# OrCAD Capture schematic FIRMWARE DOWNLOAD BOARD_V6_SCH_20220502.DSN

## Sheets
1 1. TITLE: title: Atmosic MP Download Board; rev: 06
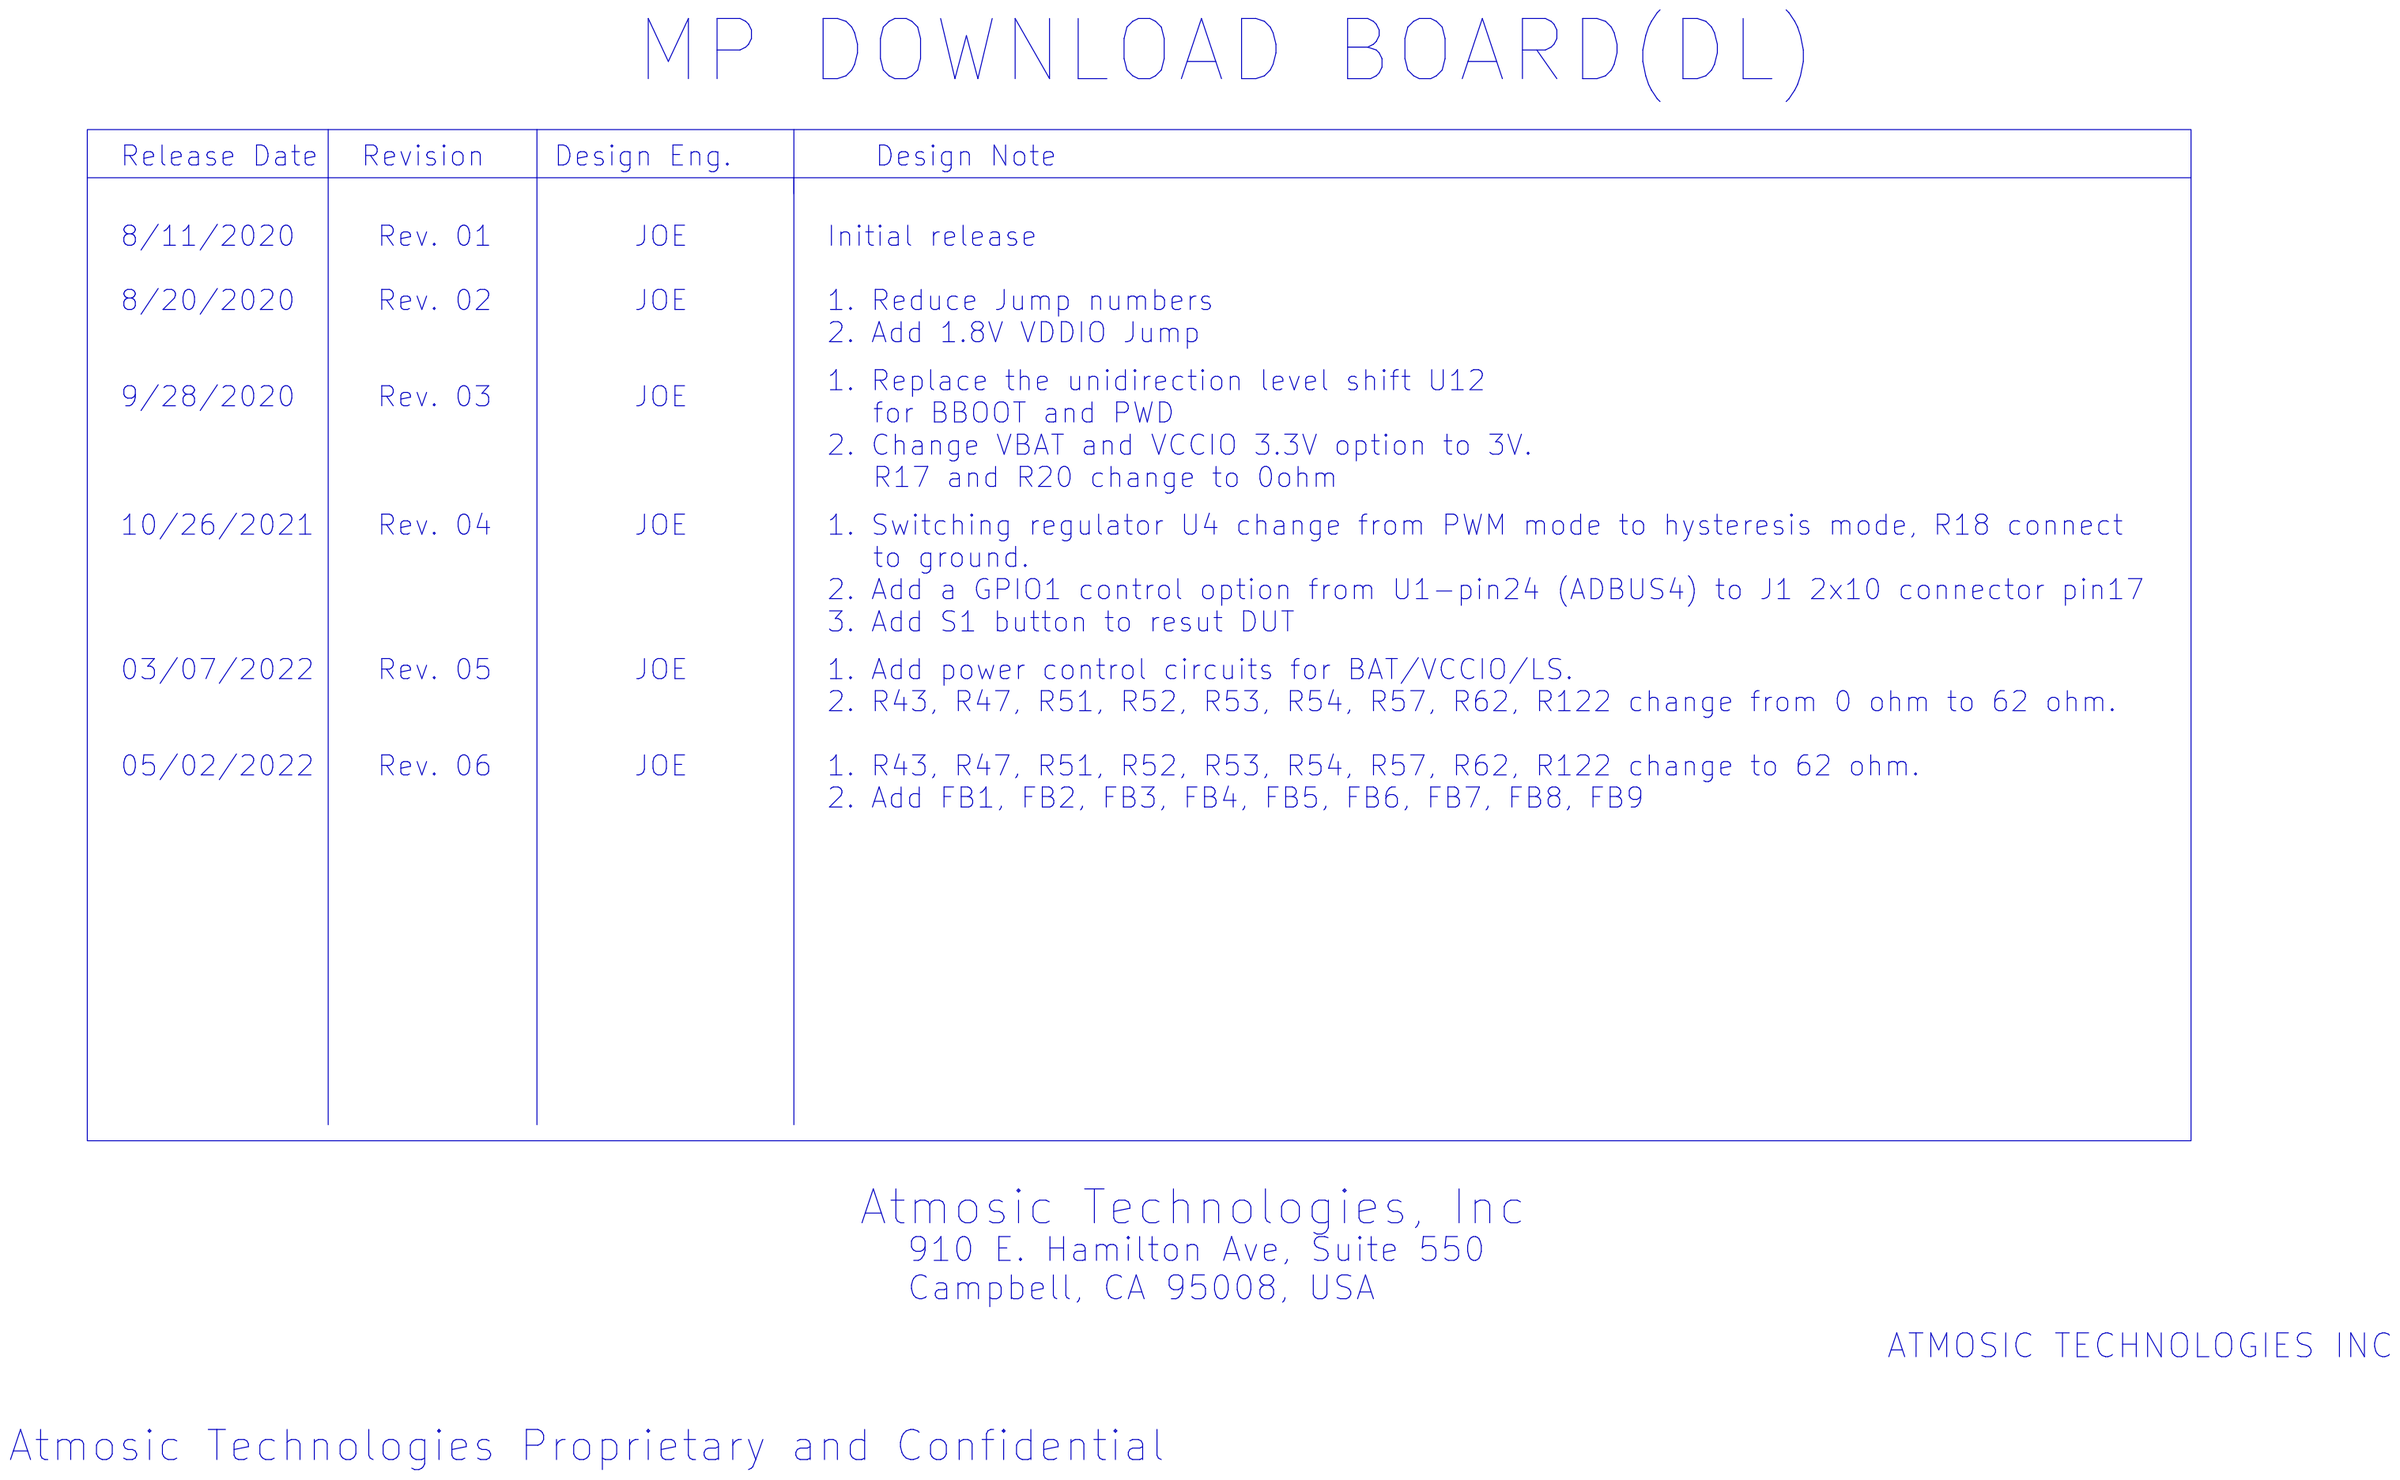
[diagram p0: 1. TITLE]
2 2. BLOCK
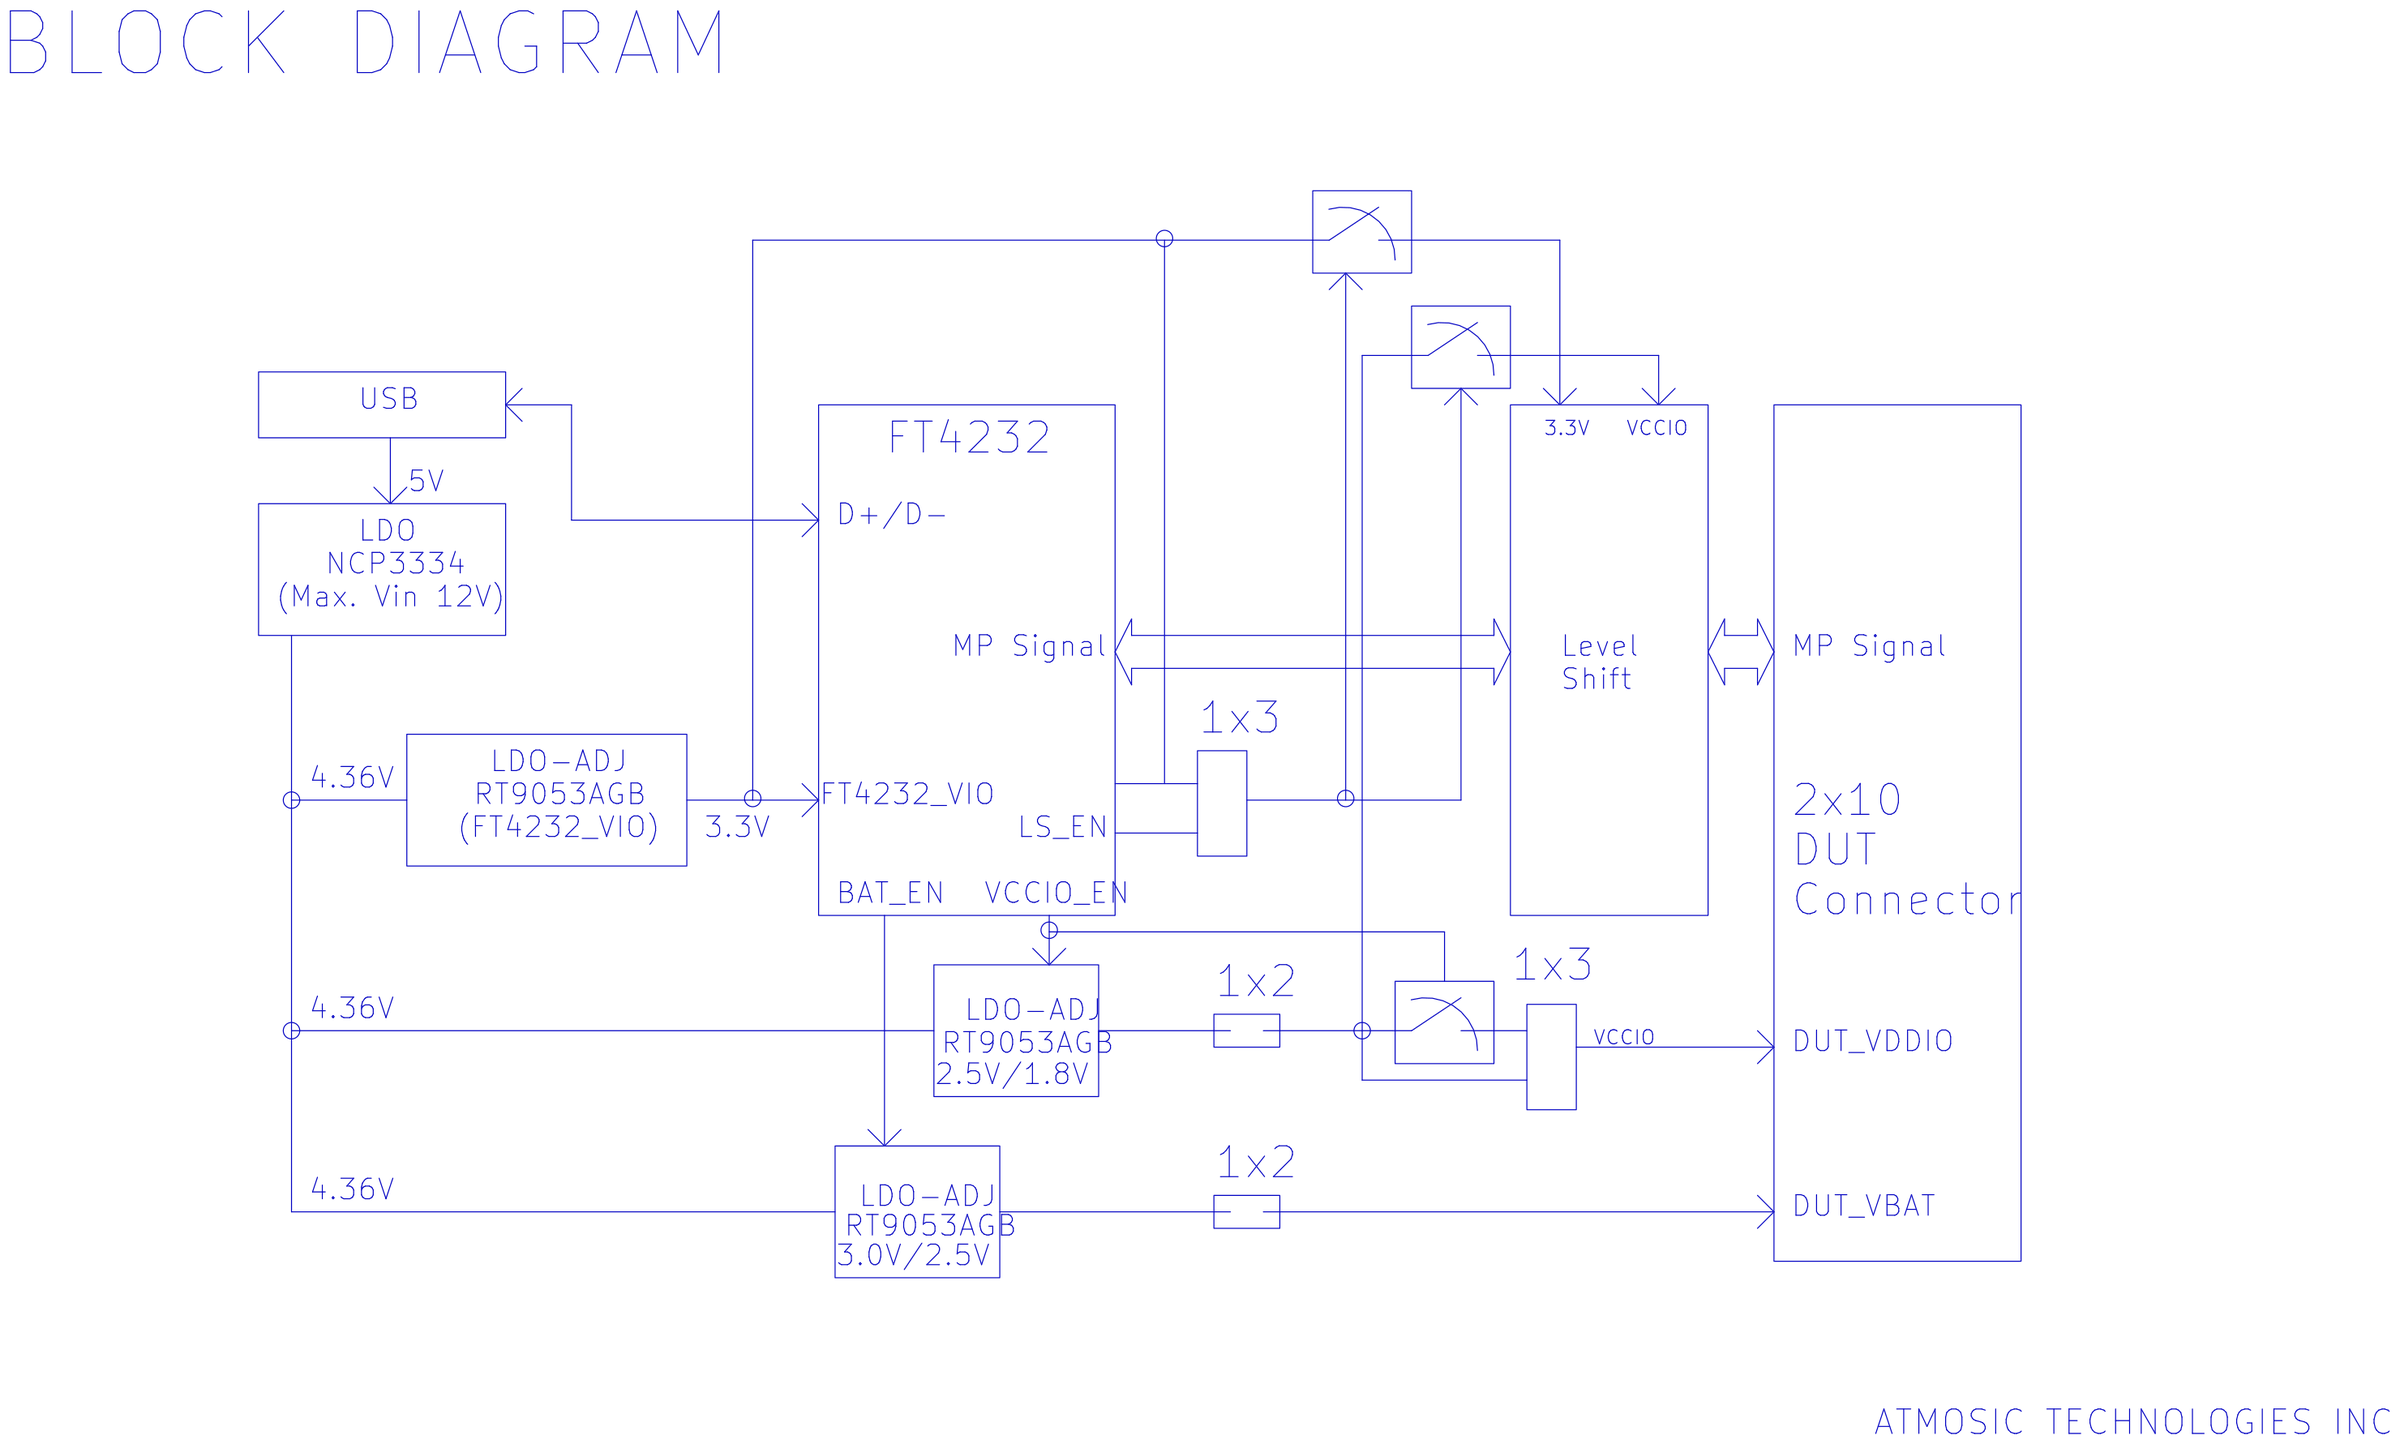
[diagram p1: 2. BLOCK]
3 3. POWER: size C
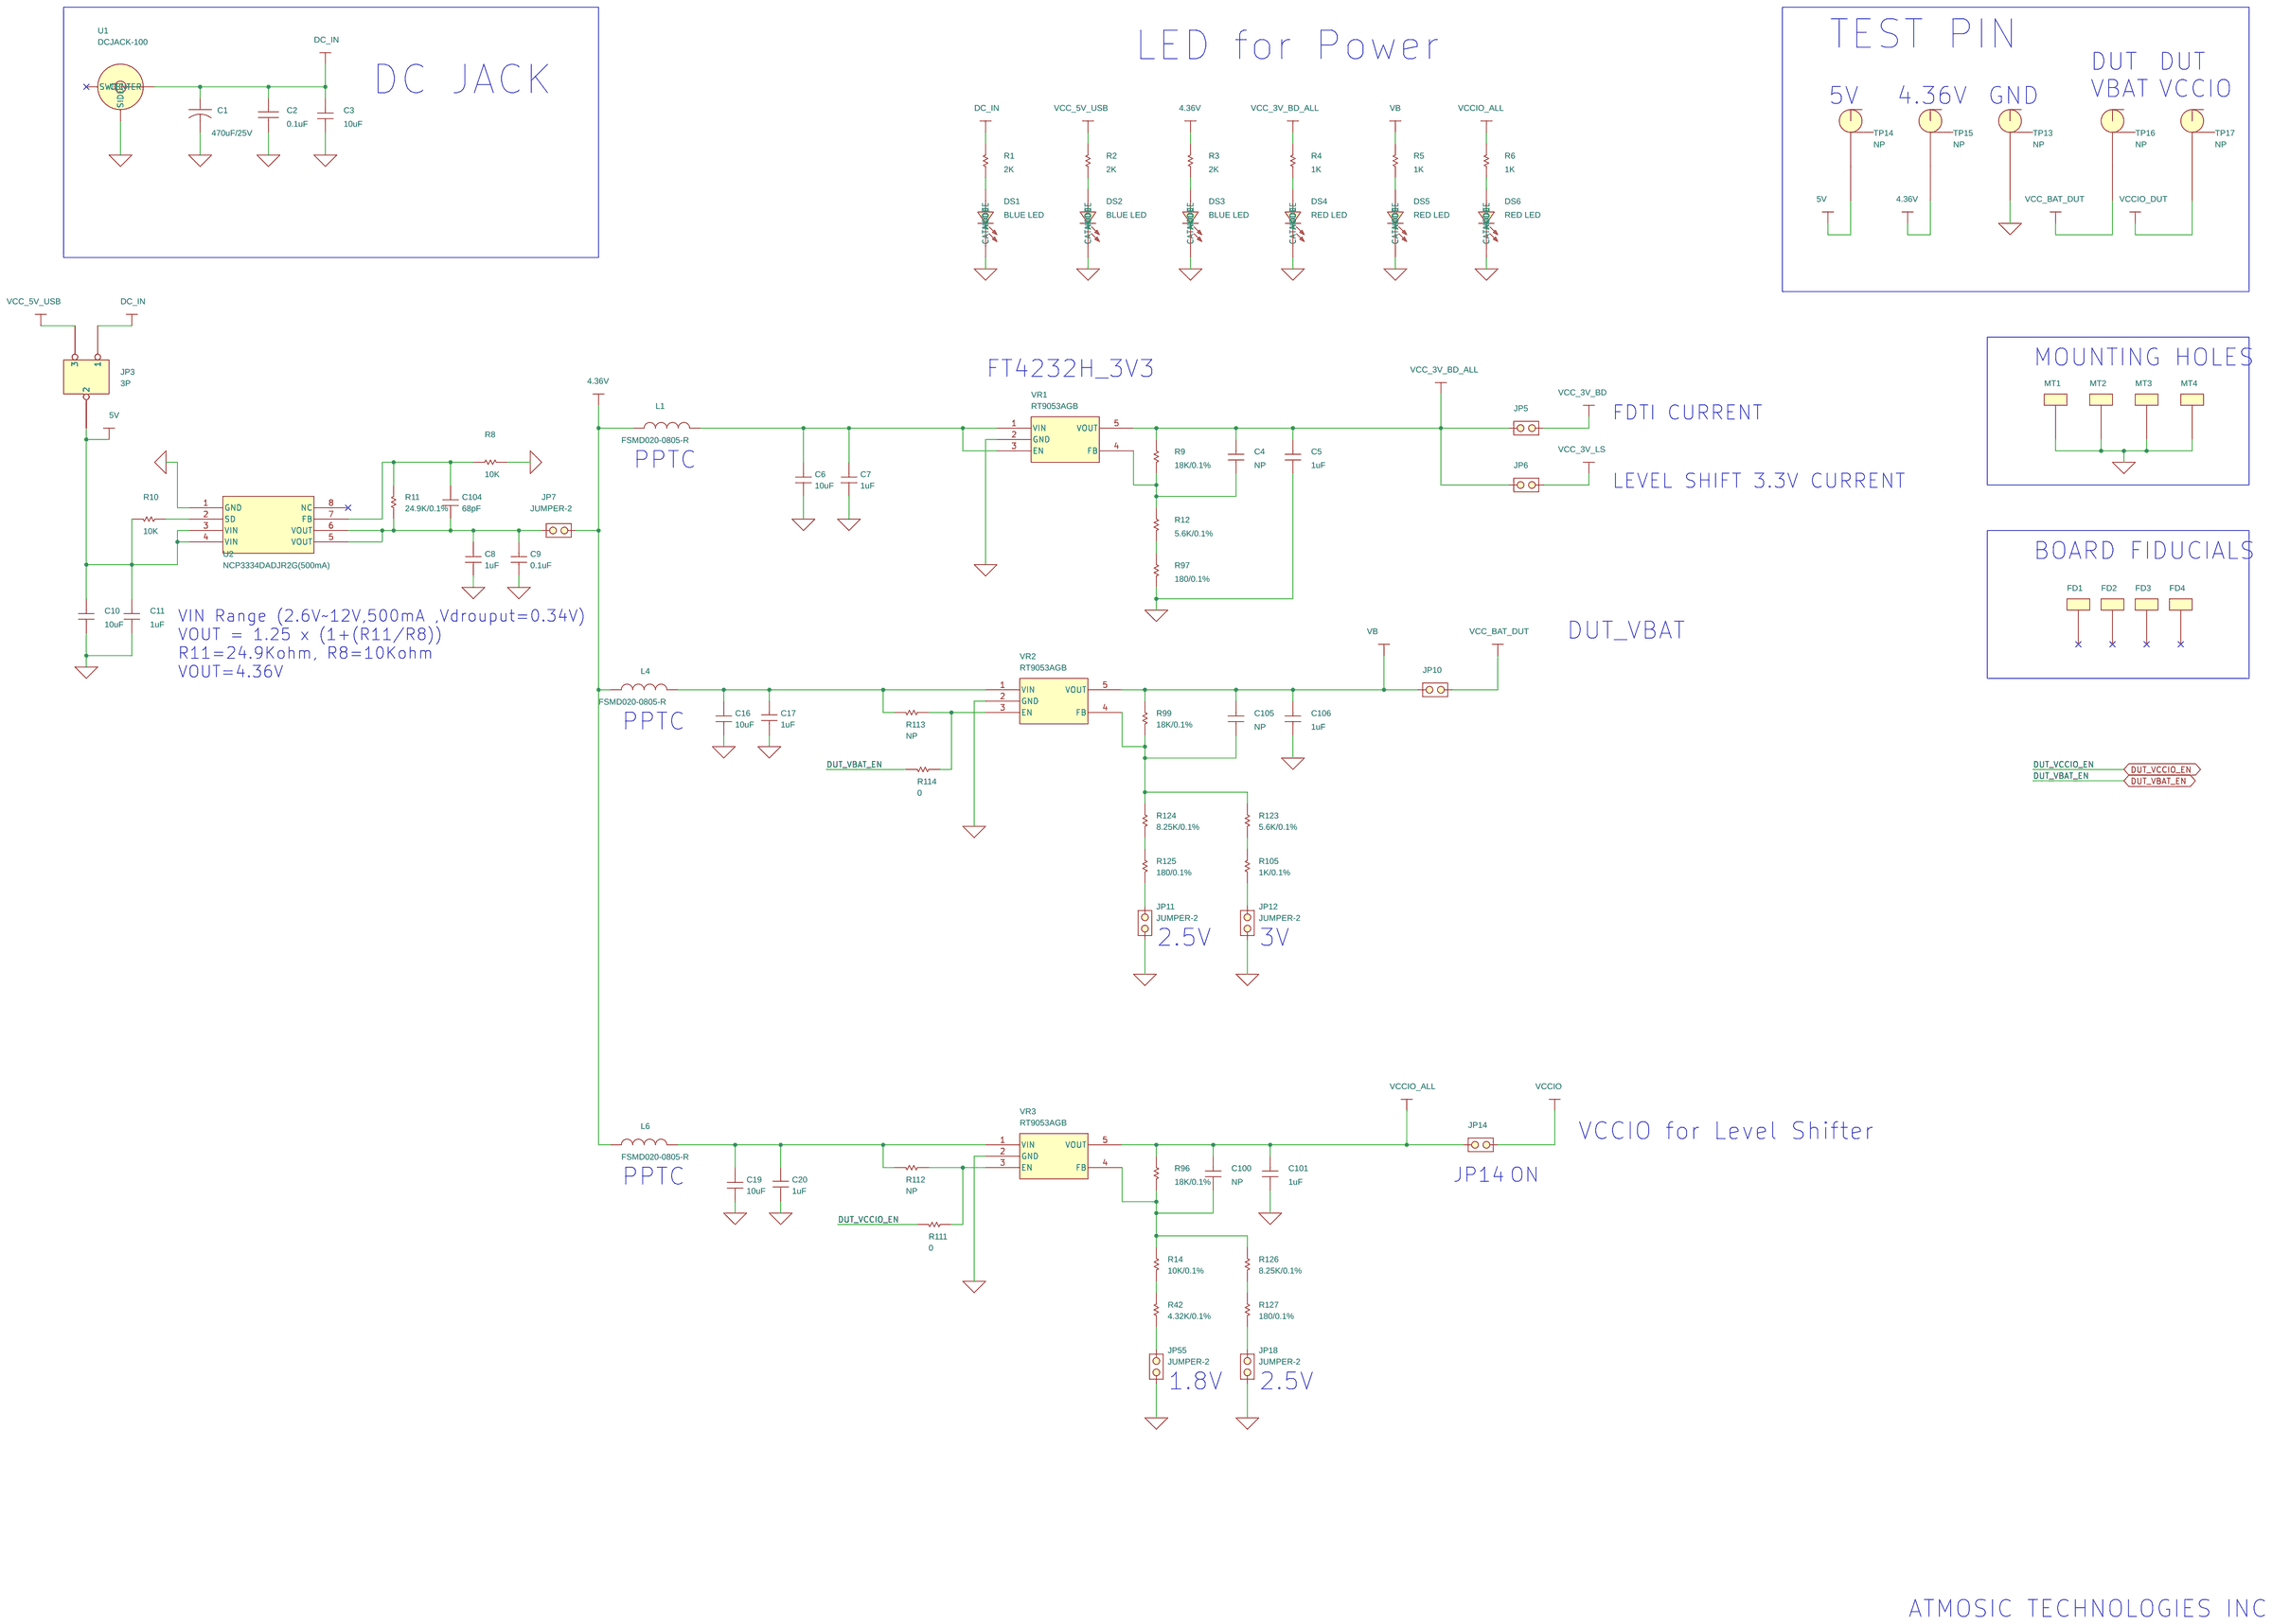
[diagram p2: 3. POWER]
4 4. FT4232H: size C
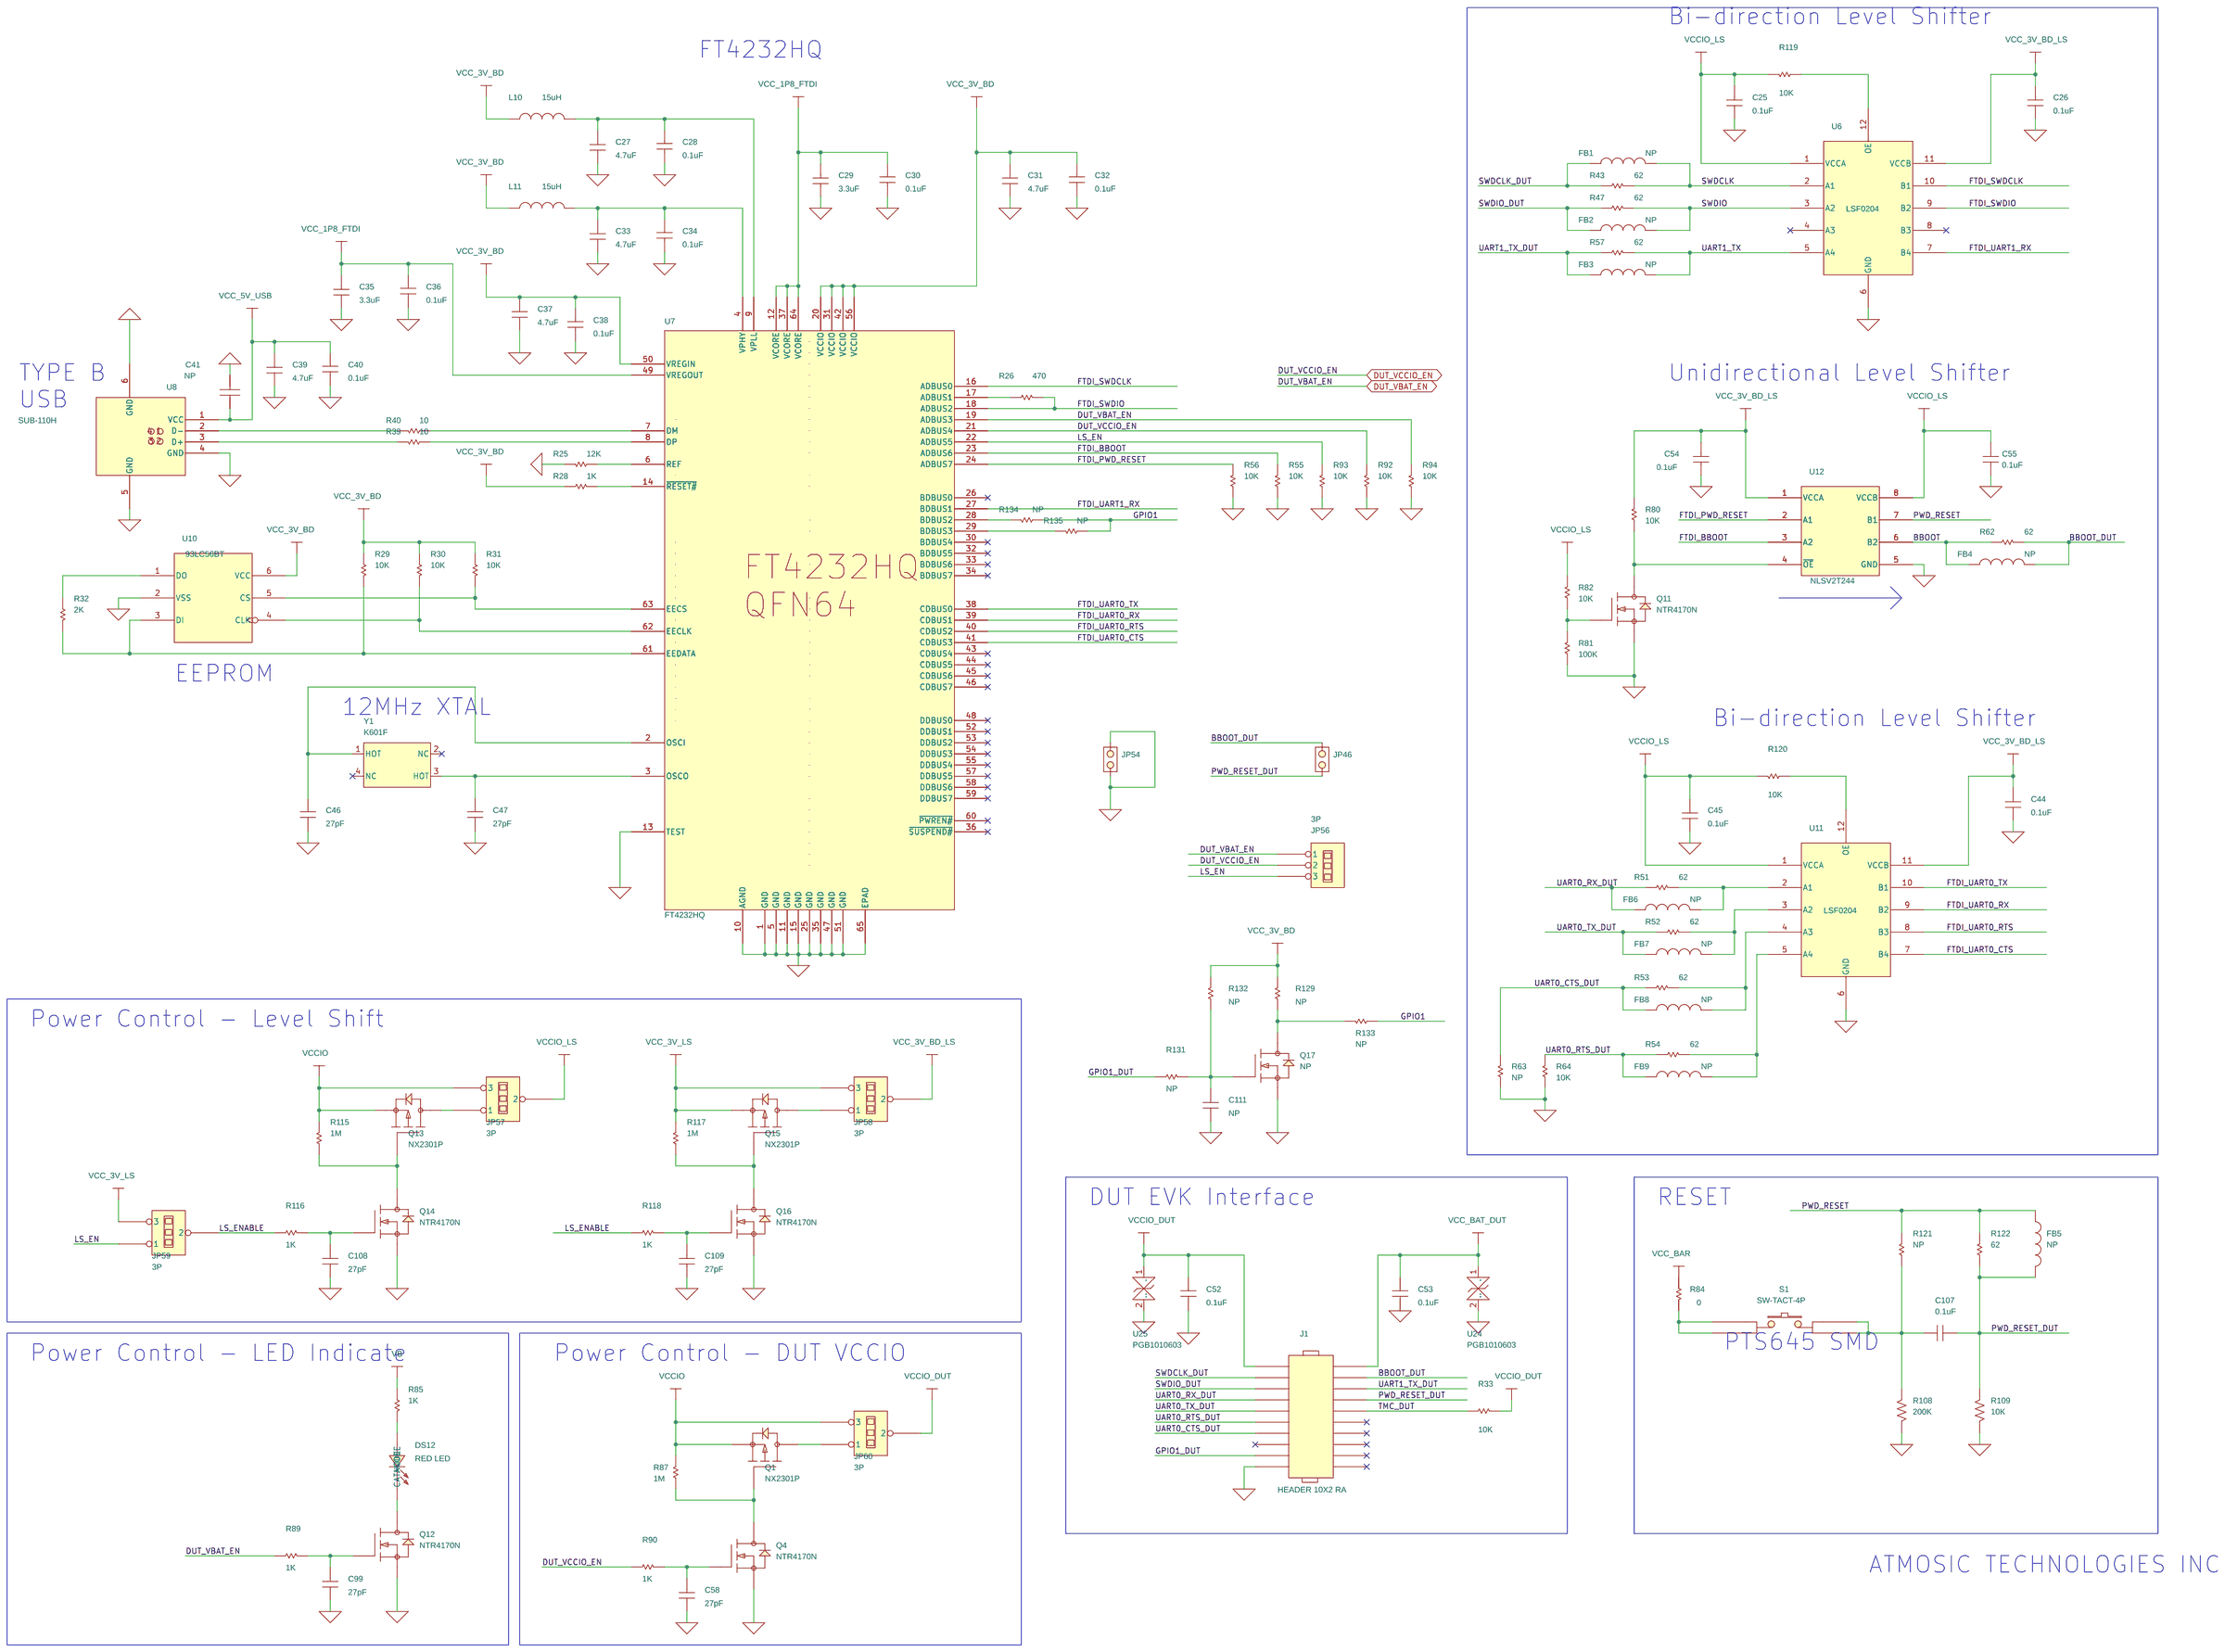
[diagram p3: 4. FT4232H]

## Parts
sheet 3. POWER
C1  470uF/25V  [EC8.3]
C2  0.1uF  [0402]
C3  10uF  [0402]
C4  NP  [0402]
C5  1uF  [0402]
C6  10uF  [0402]
C7  1uF  [0402]
C8  1uF  [0402]
C9  0.1uF  [0402]
C10  10uF  [0402]
C11  1uF  [0402]
C16  10uF  [0402]
C17  1uF  [0402]
C19  10uF  [0402]
C20  1uF  [0402]
C100  NP  [0402]
C101  1uF  [0402]
C104  68pF  [0402]
C105  NP  [0402]
C106  1uF  [0402]
DS1  BLUE LED  [LED-0603]
DS2  BLUE LED  [LED-0603]
DS3  BLUE LED  [LED-0603]
DS4  RED LED  [LED-0603]
DS5  RED LED  [LED-0603]
DS6  RED LED  [LED-0603]
FD1  TEST POINT  [FID-G]
FD2  TEST POINT  [FID-G]
FD3  TEST POINT  [FID-G]
FD4  TEST POINT  [FID-G]
JP3  3P  [HDR1X3]
JP5  JUMPER-2  [HDR1X2]
JP6  JUMPER-2  [HDR1X2]
JP7  JUMPER-2  [HDR1X2]
JP10  JUMPER-2  [HDR1X2]
JP11  JUMPER-2  [HDR1X2]
JP12  JUMPER-2  [HDR1X2]
JP14  JUMPER-2  [HDR1X2]
JP18  JUMPER-2  [HDR1X2]
JP55  JUMPER-2  [HDR1X2]
L1  FSMD020-0805-R  [0805]
L4  FSMD020-0805-R  [0805]
L6  FSMD020-0805-R  [0805]
MT1  TEST POINT  [HOLE-250R125]
MT2  TEST POINT  [HOLE-250R125]
MT3  TEST POINT  [HOLE-250R125]
MT4  TEST POINT  [HOLE-250R125]
R1  2K  [0402]
R2  2K  [0402]
R3  2K  [0402]
R4  1K  [0402]
R5  1K  [0402]
R6  1K  [0402]
R8  10K  [0402]
R9  18K/0.1%  [0402]
R10  10K  [0402]
R11  24.9K/0.1%  [0402]
R12  5.6K/0.1%  [0402]
R14  10K/0.1%  [0402]
R42  4.32K/0.1%  [0402]
R96  18K/0.1%  [0402]
R97  180/0.1%  [0402]
R99  18K/0.1%  [0402]
R105  1K/0.1%  [0402]
R111  0  [0402]
R112  NP  [0402]
R113  NP  [0402]
R114  0  [0402]
R123  5.6K/0.1%  [0402]
R124  8.25K/0.1%  [0402]
R125  180/0.1%  [0402]
R126  8.25K/0.1%  [0402]
R127  180/0.1%  [0402]
TP13  NP  [TEST1]
TP14  NP  [TEST1]
TP15  NP  [TEST1]
TP16  NP  [TEST1]
TP17  NP  [TEST1]
U1  DCJACK-100  [DCJACK-100]
U2  NCP3334DADJR2G(500mA)  [PSOP-8]
VR1  RT9053AGB  [SOT23-5]
VR2  RT9053AGB  [SOT23-5]
VR3  RT9053AGB  [SOT23-5]
sheet 4. FT4232H
C25  0.1uF  [0402]
C26  0.1uF  [0402]
C27  4.7uF  [0402]
C28  0.1uF  [0402]
C29  3.3uF  [0603]
C30  0.1uF  [0402]
C31  4.7uF  [0402]
C32  0.1uF  [0402]
C33  4.7uF  [0402]
C34  0.1uF  [0402]
C35  3.3uF  [0603]
C36  0.1uF  [0402]
C37  4.7uF  [0402]
C38  0.1uF  [0402]
C39  4.7uF  [0402]
C40  0.1uF  [0402]
C41  NP  [0402]
C44  0.1uF  [0402]
C45  0.1uF  [0402]
C46  27pF  [0402]
C47  27pF  [0402]
C52  0.1uF  [0402]
C53  0.1uF  [0402]
C54  0.1uF  [0402]
C55  0.1uF  [0402]
C58  27pF  [0402]
C99  27pF  [0402]
C107  0.1uF  [0402]
C108  27pF  [0402]
C109  27pF  [0402]
C111  NP  [0402]
DS12  RED LED  [LED-0603]
FB1  NP  [0402]
FB2  NP  [0402]
FB3  NP  [0402]
FB4  NP  [0402]
FB5  NP  [0402]
FB6  NP  [0402]
FB7  NP  [0402]
FB8  NP  [0402]
FB9  NP  [0402]
J1  HEADER 10X2 RA  [HDR10X2-RT-MATE]
JP46  JUMPER-2  [HDR1X2]
JP54  JUMPER-2  [HDR1X2]
JP56  3P  [HDR1X3]
JP57  3P  [HDR1X3]
JP58  3P  [HDR1X3]
JP59  3P  [HDR1X3]
JP60  3P  [HDR1X3]
L10  15uH  [0402]
L11  15uH  [0402]
Q1  NX2301P  [SOT23]
Q4  NTR4170N  [SOT23]
Q11  NTR4170N  [SOT23]
Q12  NTR4170N  [SOT23]
Q13  NX2301P  [SOT23]
Q14  NTR4170N  [SOT23]
Q15  NX2301P  [SOT23]
Q16  NTR4170N  [SOT23]
Q17  NP  [SOT23]
R25  12K  [0402]
R26  470  [0402]
R28  1K  [0402]
R29  10K  [0402]
R30  10K  [0402]
R31  10K  [0402]
R32  2K  [0402]
R33  10K  [0402]
R39  10  [0402]
R40  10  [0402]
R43  62  [0402]
R47  62  [0402]
R51  62  [0402]
R52  62  [0402]
R53  62  [0402]
R54  62  [0402]
R55  10K  [0402]
R56  10K  [0402]
R57  62  [0402]
R62  62  [0402]
R63  NP  [0402]
R64  10K  [0402]
R80  10K  [0402]
R81  100K  [0402]
R82  10K  [0402]
R84  0  [0603]
R85  1K  [0402]
R87  1M  [0402]
R89  1K  [0402]
R90  1K  [0402]
R92  10K  [0402]
R93  10K  [0402]
R94  10K  [0402]
R108  200K  [0402]
R109  10K  [0402]
R115  1M  [0402]
R116  1K  [0402]
R117  1M  [0402]
R118  1K  [0402]
R119  10K  [0402]
R120  10K  [0402]
R121  NP  [0402]
R122  62  [0402]
R129  NP  [0402]
R131  NP  [0402]
R132  NP  [0402]
R133  NP  [0402]
R134  NP  [0402]
R135  NP  [0402]
S1  SW-TACT-4P  [SWI-SM-PTS645]
U6  LSF0204  [QFN-12-1.7X2_1]
U7  FT4232HQ  [QFN-64-9X9MM-0.5]
U8  SUB-110H  [SUB-110H]
U10  93LC56BT  [SOT23-6]
U11  LSF0204  [QFN-12-1.7X2_1]
U12  NLSV2T244  [UDFN-8-1.8X1.2-0.4P]
U24  PGB1010603  [0603]
U25  PGB1010603  [0603]
Y1  K601F  [CRY-SMD4-3.2X2.5MM]

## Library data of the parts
C1 = C: MF: Panasonic Electronic; Part Number: EEU-FM1H471
C2 = CAP_NP: MF: Murata Electronics; Part Number: GRM155R71H104KE14D
C3 C6 C10 C16 C19 = SMALL_CAP: MF: Murata Electronics; Part Number: GRM155R60J106ME15D
C4 C100 C105 C111 = SMALL_CAP
C5 C7 C8 C11 C17 C20 C101 C106 = SMALL_CAP: MF: Murata Electronics; Part Number: GRM155R61C105KA12
C9 C25 C26 C28 C30 C32 C34 C36 C38 C40 C44 C45 C52-C55 C107 = SMALL_CAP: MF: Murata Electronics; Part Number: GRM155R71H104KE14D
C104 = SMALL_CAP: MF: WALSIN; Part Number: 0402N680J500CT
DS1-DS3 = LED: MF: Lite-On Inc.; Part Number: LTST-C191TBKT
DS4-DS6 DS12 = LED: MF: Lite-On Inc.; Part Number: LTST-C191KRKT
FD1-FD4 MT1-MT4 = TEST_POINT
JP3 = HEADER_3_0: MF: Amphenol FCI; Package Type: SIP-3P; Part Number: 68001-203HLF
JP5-JP7 JP10-JP12 JP14 JP18 JP46 JP54 JP55 = JUMPER-2: MF: Amphenol ICC (FCI); Part Number: 68000-102HLF
L1 L4 L6 = INDUCTOR: MF: Fuxetec
R1-R3 R32 = SMALL_R1: MF: WALSIN; Part Number: WR04X2001FTL
R4-R6 R28 R85 R89 R90 R116 R118 = SMALL_R1: MF: WALSIN; Part Number: WR04X1001FTL
R8 R10 R29-R31 R33 R55 R56 R64 R80 R82 R92-R94 R119 R120 = SMALL_R1: MF: WALSIN; Part Number: WR04X1002FTL
R9 R96 R99 = SMALL_R1: MF: YAGEO; Part Number: RT0402BRE0718KL
R11 = SMALL_R1: MF: Panasonic Electronic; Part Number: ERA-2AEB2492X
R12 R123 = SMALL_R1: MF: Panasonic Electronic; Part Number: ERA-2AEB562X
R14 = SMALL_R1: MF: Panasonic Electronic; Part Number: ERA-2AEB103X
R42 = SMALL_R1: MF: Vishay; Part Number: TNPW04024K32BEED
R97 R125 R127 = SMALL_R1: MF: Panasonic Electronic; Part Number: ERA-2VEB1800X
R105 = SMALL_R1: MF: KOA; Part Number: RN73H1ETTP1001B25
R111 R114 = SMALL_R1: MF: WALSIN; Part Number: WR04X0000FTL
R63 R112 R113 R121 R129 R131-R135 = SMALL_R1
R124 R126 = SMALL_R1: MF: Panasonic Electronic; Part Number: ERA-2AEB8251X
TP13-TP17 = TP_0
U1 = DCJACK-100: MF: CUI Devices
U2 = AP2318AMP-ADJTRG1_0: MF: ON Semiconductor; Part Number: NCP3334DADJR2G
VR1 = VAR_REG_0: MF: RICHTEK
VR2 VR3 = VAR_REG_0: MF: Diodes Incorporated; Part Number: AP2127K-ADJTRG1
C27 C31 C33 C37 C39 = SMALL_CAP: MF: Murata Electronics; Part Number: GRM155R60J475ME47D
C29 C35 = SMALL_CAP: MF: TDK Corporation; Part Number: C1608JB1C335K080AC
C41 = CAP_NP
C46 C47 C58 C99 C108 C109 = SMALL_CAP: MF: WALSIN; Part Number: 0402N270J500CT
FB1-FB9 = INDUCTOR: MF: Murata
J1 = HEADER_10X2: MF: Sullins Connector Solutions; Part Number: SFH11-PBPC-D10-RA-BK
JP56 = HEADER_3_2: MF: Amphenol FCI; Package Type: SIP-3P; Part Number: 68001-203HLF
JP57 = HEADER_3_1_1: MF: Amphenol FCI; Package Type: SIP-3P; Part Number: 68001-203HLF
JP58 = HEADER_3_1: MF: Amphenol FCI; Package Type: SIP-3P; Part Number: 68001-203HLF
JP59 = HEADER_3_1_3: MF: Amphenol FCI; Package Type: SIP-3P; Part Number: 68001-203HLF
JP60 = HEADER_3_1_2: MF: Amphenol FCI; Package Type: SIP-3P; Part Number: 68001-203HLF
L10 L11 = INDUCTOR: MF: Murata Electronics; Part Number: BLM15KD300SN1D
Q1 Q13 Q15 = PWRMOSFET_EP_GSD_0: MF: Nexperia USA Inc.; Part Number: NX2301P,215
Q4 Q11 Q12 Q14 Q16 = MPF990_0: MF: ON Semiconductor; Part Number: NTR4170NT1G
Q17 = MPF990_0
R25 = SMALL_R1: MF: WALSIN; Part Number: WR04X1202FTL
R26 = SMALL_R1: MF: WALSIN; Part Number: WR04X4700FTL
R39 R40 = SMALL_R1: MF: TA-I; Part Number: RM04FTN10R0
R43 R47 R51-R54 R57 R62 R122 = SMALL_R1: MF: YAGEO; Part Number: WR04X62R0FTL
R81 = SMALL_R1: MF: WALSIN; Part Number: WR04X1003FTL
R84 = SMALL_R1: MF: WALSIN; Part Number: WR06X000 PTL
R87 R115 R117 = SMALL_R1: MF: YAGEO; Part Number: RC0402JR-071ML
R108 = R_0: MF: YAGEO; Part Number: RC0402FR-07200KL
R109 = R_0: MF: WALSIN; Part Number: WR04X1002FTL
S1 = SW-TACT-4P-5
U6 U11 = NTB0104: MF: Texas Instruments; Part Number: LSF0204RUTR
U7 = FT4232HQ-REEL_3: MF: FDTI
U8 = MiniUSB_0: MF: Contact Technology Corp.
U10 = 93LC56BT-I_OT: MF: Microchip Technology; Part Number: 93LC56BT-I/OT
U12 = NLSV2T244: MF: ON Semiconductor; Part Number: NLSV2T244MUTAG
U24 U25 = PGB1010603: MF: Littelfuse Inc.; Part Number: PGB1010603MR
Y1 = XTAL-OSC-4P_0: MF: Kyocera; Part Number: CX3225SB12000H0FLJCC

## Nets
4.36V: JP7.2 L1.1 L4.1 L6.1 R3.2 TP15.1(TP)
5V: C10.2 C11.2 JP3.2 R10.2 TP14.1(TP) U2.3(VIN) U2.4(VIN)
GND_SIGNAL: C1.2 C2.2 C3.1 C5.1 C6.1 C7.1 C8.1 C9.1 C10.1 C11.1 C16.1 C17.2 C19.1 C20.2 C25.1 C26.1 C27.1 C28.2 C29.1 C30.2 C31.1 C32.2 C33.1 C34.2 C35.1 C36.2 C37.1 C38.2 C39.1 C40.2 C41.2 C44.1 C45.1 C46.2 C47.2 C52.2 C53.2 C54.1 C55.1 C58.1 C99.1 C101.1 C106.1 C108.1 C109.1 C111.1 DS1.1(CATHODE) DS2.1(CATHODE) DS3.1(CATHODE) DS4.1(CATHODE) DS5.1(CATHODE) DS6.1(CATHODE) J1.19 JP11.2 JP12.2 JP18.2 JP54.1 JP54.2 JP55.2 MT1.1 MT2.1 MT3.1 MT4.1 Q4.2(SOURCE) Q11.2(SOURCE) Q12.2(SOURCE) Q14.2(SOURCE) Q16.2(SOURCE) Q17.2(SOURCE) R8.2 R25.2 R55.1 R56.1 R63.1 R64.1 R81.1 R92.1 R93.1 R94.1 R97.2 R108.1 R109.1 TP13.1(TP) U1.1(SIDE) U2.1(GND) U6.6(GND) U7.1(GND) U7.5(GND) U7.10(AGND) U7.11(GND) U7.13(TEST) U7.15(GND) U7.25(GND) U7.35(GND) U7.47(GND) U7.51(GND) U7.65(EPAD) U8.4(GND) U8.5(GND) U8.6(GND) U10.2(VSS) U11.6(GND) U12.5(GND) U24.2(..) U25.2(..) VR1.2(GND) VR2.2(GND) VR3.2(GND)
VCC_1P8_FTDI: C29.2 C30.1 C35.2 C36.1 U7.12(VCORE) U7.37(VCORE) U7.49(VREGOUT) U7.64(VCORE)
VCC_3V_BD: C31.2 C32.1 C37.2 C38.1 JP5.2 L10.1 L11.1 R28.1 R29.1 R30.1 R31.1 R129.1 R132.1 U7.20(VCCIO) U7.31(VCCIO) U7.42(VCCIO) U7.50(VREGIN) U7.56(VCCIO) U10.6(VCC)
VCC_3V_BD_ALL: C4.2 C5.2 JP5.1 JP6.1 R4.2 R9.1 VR1.5(VOUT)
VCC_3V_BD_LS: C26.2 C44.2 C54.2 JP58.2 R80.2 U6.11(VCCB) U11.11(VCCB) U12.1(VCCA)
VCC_3V_LS: JP6.2 JP58.3 JP59.3 Q15.2(SOURCE) R117.1
VCC_5V_USB: C39.2 C40.1 C41.1 JP3.3 R2.2 U8.1(VCC)
VCC_BAT_DUT: C53.1 J1.2 JP10.2 TP16.1(TP) U24.1(.)
VCCIO: JP14.2 JP57.3 JP60.3 Q1.2(SOURCE) Q13.2(SOURCE) R87.1 R115.1
VCCIO_ALL: C100.2 C101.2 JP14.1 R6.2 R96.1 VR3.5(VOUT)
VCCIO_DUT: C52.1 J1.1 JP60.2 R33.1 R84.1 TP17.1(TP) U25.1(.)
VCCIO_LS: C25.2 C45.2 C55.2 JP57.2 R82.2 R119.2 R120.2 U6.1(VCCA) U11.1(VCCA) U12.8(VCCB)
BBOOT: FB4.1 R62.1 U12.6(B2)
BBOOT_DUT: FB4.2 J1.4 JP46.2 R62.2
DC_IN: C1.1 C2.1 C3.2 JP3.1 R1.2 U1.3(CENTER)
DUT_VBAT_EN: JP56.1 R89.2 R94.2 R114.1 U7.19(ADBUS3)
DUT_VCCIO_EN: JP56.2 R90.2 R92.2 R111.1 U7.21(ADBUS4)
FTDI_BBOOT: R55.2 U7.23(ADBUS6) U12.3(A2)
FTDI_PWD_RESET: R56.2 U7.24(ADBUS7) U12.2(A1)
FTDI_SWDCLK: U6.10(B1) U7.16(ADBUS0)
FTDI_SWDIO: R26.2 U6.9(B2) U7.18(ADBUS2)
FTDI_UART0_CTS: U7.41(CDBUS3) U11.7(B4)
FTDI_UART0_RTS: U7.40(CDBUS2) U11.8(B3)
FTDI_UART0_RX: U7.39(CDBUS1) U11.9(B2)
FTDI_UART0_TX: U7.38(CDBUS0) U11.10(B1)
FTDI_UART1_RX: U6.7(B4) U7.27(BDBUS1)
GPIO1: R133.2 R134.1 R135.1
GPIO1_DUT: J1.17 R131.2
LS_EN: JP56.3 JP59.1 R93.2 U7.22(ADBUS5)
LS_ENABLE: JP59.2 R116.2 R118.2
PWD_RESET: FB5.1 R121.1 R122.1 U12.7(B1)
PWD_RESET_DUT: C107.2 FB5.2 J1.8 JP46.1 R109.2 R122.2
SWDCLK: FB1.2 R43.2 U6.2(A1)
SWDCLK_DUT: FB1.1 J1.3 R43.1
SWDIO: FB2.2 R47.2 U6.3(A2)
SWDIO_DUT: FB2.1 J1.5 R47.1
TMC_DUT: J1.10 R33.2
UART0_CTS_DUT: FB8.1 J1.13 R53.1 R63.2
UART0_RTS_DUT: FB9.1 J1.11 R54.1 R64.2
UART0_RX_DUT: FB6.1 J1.7 R51.1
UART0_TX_DUT: FB7.1 J1.9 R52.1
UART1_TX: FB3.2 R57.2 U6.5(A4)
UART1_TX_DUT: FB3.1 J1.6 R57.1
VB: C105.2 C106.2 JP10.1 R5.2 R85.1 R99.1 VR2.5(VOUT)
N16857263: C6.2 C7.2 L1.2 VR1.1(VIN) VR1.3(EN)
N16857297: C4.1 R9.2 R12.1 VR1.4(FB)
N16857401: C16.2 C17.1 L4.2 R113.1 VR2.1(VIN)
N16857596: C19.2 C20.1 L6.2 R112.1 VR3.1(VIN)
N16857743: JP18.1 R127.2
N16860548: C27.2 C28.1 L10.2 U7.9(VPLL)
N16860666: C33.2 C34.1 L11.2 U7.4(VPHY)
N16860980: R26.1 U7.17(ADBUS1)
N16861063: R25.1 U7.6(REF)
N16861081: R28.2 U7.14(~{RESET#})
N16861161: R32.1 U10.1(DO)
N16861167: R29.2 R32.2 U7.61(EEDATA) U10.3(DI)
N16861169: R30.2 U7.62(EECLK) U10.4(CLK)
N16861171: R31.2 U7.63(EECS) U10.5(CS)
N16861233: C46.1 U7.2(OSCI) Y1.1(HOT)
N16861281: C47.1 U7.3(OSCO) Y1.3(HOT)
N16868677: FB6.2 R51.2 U11.2(A1)
N16868695: FB7.2 R52.2 U11.3(A2)
N16868713: FB9.2 R54.2 U11.5(A4)
N16868731: FB8.2 R53.2 U11.4(A3)
N16880316: DS1.2(ANODE) R1.1
N16880318: DS2.2(ANODE) R2.1
N16880320: DS3.2(ANODE) R3.1
N16880322: DS4.2(ANODE) R4.1
N16880324: DS5.2(ANODE) R5.1
N16880326: DS6.2(ANODE) R6.1
N16961290: R10.1 U2.2(SD)
N16962750: C8.2 C9.2 C104.1 JP7.1 R11.1 U2.5(VOUT) U2.6(VOUT)
N16963260: C104.2 R8.1 R11.2 U2.7(FB)
N17120306: R40.1 U7.7(DM)
N17120315: R40.2 U8.2(D-)
N17120320: R39.2 U8.3(D+)
N17120323: R39.1 U7.8(DP)
N17126405: JP55.1 R42.2
N17165039: R84.2 S1.1 S1.2
N17165055: C107.1 R108.2 R121.2 S1.3 S1.4
N17169241: DS12.2(ANODE) R85.2
N17169249: JP60.1 Q1.3(DRAIN)
N17169283: Q1.1(GATE) Q4.3(DRAIN) R87.2
N17169291: DS12.1(CATHODE) Q12.3(DRAIN)
N17169369: C99.2 Q12.1(GATE) R89.1
N17169377: C58.2 Q4.1(GATE) R90.1
N17172597: Q11.3(DRAIN) R80.1 U12.4(~{OE})
N17172624: Q11.1(GATE) R81.2 R82.1
N17179216: C100.1 R14.1 R96.2 R126.1 VR3.4(FB)
N17184341: R12.2 R97.1
N17190503: R14.2 R42.1
N17192597: C105.1 R99.2 R123.1 R124.1 VR2.4(FB)
N17192665: R124.2 R125.1
N17192685: JP11.1 R125.2
N17193181: R105.1 R123.2
N17193191: JP12.1 R105.2
N17207291: R111.2 R112.2 VR3.3(EN)
N17207454: R113.2 R114.2 VR2.3(EN)
N17208876: JP57.1 Q13.3(DRAIN)
N17208886: Q13.1(GATE) Q14.3(DRAIN) R115.2
N17208914: C108.2 Q14.1(GATE) R116.1
N17209244: JP58.1 Q15.3(DRAIN)
N17209254: Q15.1(GATE) Q16.3(DRAIN) R117.2
N17209282: C109.2 Q16.1(GATE) R118.1
N17210044: R119.1 U6.12(OE)
N17210135: R120.1 U11.12(OE)
N17213032: R126.2 R127.1
N17224602: Q17.3(DRAIN) R129.2 R133.1
N17224624: C111.2 Q17.1(GATE) R131.1 R132.2
N17226457: R134.2 U7.28(BDBUS2)
N17226460: R135.2 U7.29(BDBUS3)

Not connected (* = marked no-connect by the designer): FD1 1*; FD2 1*; FD3 1*; FD4 1*; J1 12* 14* 15* 16* 18* 20*; U1 2(SWITCH)*; U2 8(NC)*; U6 4(A3)* 8(B3)*; U7 26(BDBUS0)* 30(BDBUS4)* 32(BDBUS5)* 33(BDBUS6)* 34(BDBUS7)* 36(~{SUSPEND#})* 43(CDBUS4)* 44(CDBUS5)* 45(CDBUS6)* 46(CDBUS7)* 48(DDBUS0)* 52(DDBUS1)* 53(DDBUS2)* 54(DDBUS3)* 55(DDBUS4)* 57(DDBUS5)* 58(DDBUS6)* 59(DDBUS7)* 60(~{PWREN#})*; Y1 2(NC)* 4(NC)*

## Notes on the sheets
sheet 1
- MP DOWNLOAD BOARD(DL)
- Release Date
- Revision
- Design Eng.
- Design Note
- 8/11/2020
- Rev. 01
- JOE
- Initial release
- 8/20/2020
- Rev. 02
- JOE
- 1. Reduce Jump numbers
  2. Add 1.8V VDDIO Jump
- 1. Replace the unidirection level shift U12
     for BBOOT and PWD
  2. Change VBAT and VCCIO 3.3V option to 3V.
     R17 and R20 change to 0ohm
- 9/28/2020
- Rev. 03
- JOE
- 10/26/2021
- Rev. 04
- JOE
- 1. Switching regulator U4 change from PWM mode to hysteresis mode, R18 connect
     to ground.
  2. Add a GPIO1 control option from U1-pin24 (ADBUS4) to J1 2x10 connector pin17
  3. Add S1 button to resut DUT
- 03/07/2022
- Rev. 05
- JOE
- 1. Add power control circuits for BAT/VCCIO/LS.
- 2. R43, R47, R51, R52, R53, R54, R57, R62, R122 change from 0 ohm to 62 ohm.
- 05/02/2022
- Rev. 06
- JOE
- 1. R43, R47, R51, R52, R53, R54, R57, R62, R122 change to 62 ohm.
- 2. Add FB1, FB2, FB3, FB4, FB5, FB6, FB7, FB8, FB9
- Atmosic Technologies, Inc
- 910 E. Hamilton Ave, Suite 550
  Campbell, CA 95008, USA
- ATMOSIC TECHNOLOGIES INC
- Atmosic Technologies Proprietary and Confidential
sheet 2
- BLOCK DIAGRAM
- USB
- FT4232
- 3.3V
- VCCIO
- 5V
- D+/D-
- LDO
- NCP3334
- (Max. Vin 12V)
- MP Signal
- Level
  Shift
- MP Signal
- 1x3
- LDO-ADJ
- 4.36V
- RT9053AGB
- FT4232_VIO
- 2x10
  DUT
  Connector
- (FT4232_VIO)
- 3.3V
- LS_EN
- BAT_EN
- VCCIO_EN
- 1x3
- 1x2
- 4.36V
- LDO-ADJ
- RT9053AGB
- VCCIO
- DUT_VDDIO
- 2.5V/1.8V
- 1x2
- 4.36V
- LDO-ADJ
- DUT_VBAT
- RT9053AGB
- 3.0V/2.5V
- ATMOSIC TECHNOLOGIES INC
sheet 3
- TEST PIN
- LED for Power
- DUT
  VBAT
- DUT
  VCCIO
- DC JACK
- 5V
- 4.36V
- GND
- MOUNTING HOLES
- FT4232H_3V3
- FDTI CURRENT
- PPTC
- LEVEL SHIFT 3.3V CURRENT
- BOARD FIDUCIALS
- VIN Range (2.6V~12V,500mA ,Vdrouput=0.34V)
  VOUT = 1.25 x (1+(R11/R8))
  R11=24.9Kohm, R8=10Kohm
  VOUT=4.36V
- DUT_VBAT
- PPTC
- 2.5V
- 3V
- VCCIO for Level Shifter
- PPTC
- JP14
- ON
- 1.8V
- 2.5V
- ATMOSIC TECHNOLOGIES INC
sheet 4
- Bi-direction Level Shifter
- FT4232HQ
- TYPE B
  USB
- Unidirectional Level Shifter
- EEPROM
- 12MHz XTAL
- Bi-direction Level Shifter
- Power Control - Level Shift
- DUT EVK Interface
- RESET
- PTS645 SMD
- Power Control - LED Indicate
- Power Control - DUT VCCIO
- ATMOSIC TECHNOLOGIES INC
